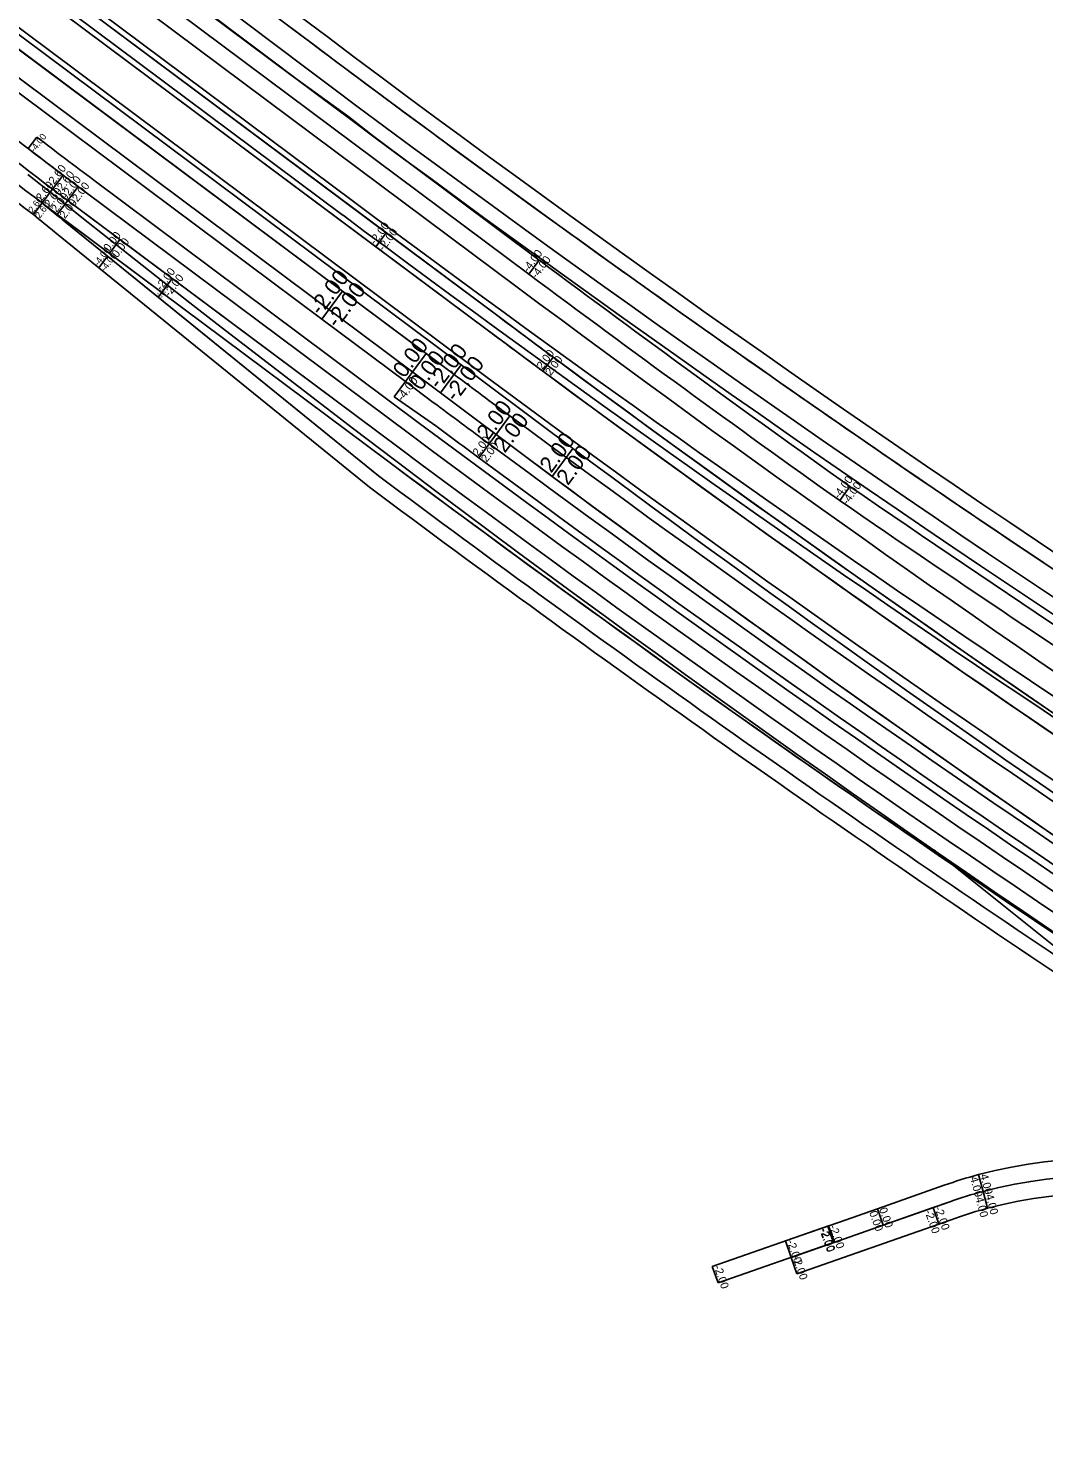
# Model space of a CAD drawing. Extents: x 2342222 to 2351711, y 366548 to 372860.
# Drawn here: x 2344990 to 2345691, y 369795 to 370762 of the extents above; entities that cross this region are included whole.
import ezdxf

# ---------------------------------------------------------------- set-up
doc = ezdxf.new("R2010")
doc.units = 0
for name, color, linetype in [('RD_HC_Cl', 7, 'Continuous'), ('RD_PD_Final_LnLine', 7, 'Continuous'), ('RD_PD_PaveShd', 7, 'Continuous'), ('RD_PD_SuperShp_BL_EB_526', 7, 'Continuous'), ('RD_PD_SuperShp_BL_WB_526', 7, 'Continuous'), ('RD_PD_SuperShp_EB_526', 7, 'Continuous'), ('RD_PD_SuperShp_LINE-A', 7, 'Continuous'), ('RD_PD_SuperShp_REL_L-2118', 7, 'Continuous'), ('RD_PD_SuperShp_REL_LINE-3', 7, 'Continuous'), ('RD_PD_SuperShp_WB_526', 7, 'Continuous')]:
    doc.layers.add(name, color=color, linetype=linetype)

msp = doc.modelspace()

# ---------------------------------------------------------------- linework, layer by layer
at = {"layer": 'RD_HC_Cl'}
msp.add_line((2345614.6, 370194.71), (2346103.37, 369803.49), dxfattribs=at)
msp.add_line((2345614.6, 370194.71), (2346103.37, 369803.49), dxfattribs=at)
at = {"layer": 'RD_PD_Final_LnLine'}
msp.add_arc((2351872.76, 379241.01), 11000, 231.263715, 239.178507, dxfattribs=at)
msp.add_arc((2351872.76, 379241.01), 11000, 231.263715, 239.178507, dxfattribs=at)
at = {"layer": 'RD_PD_PaveShd'}
for p, q in [((2344136.54, 371426.71), (2345306.62, 370553.4)), ((2344797.16, 371008.51), (2345171.34, 370729.24)), ((2345171.34, 370729.24), (2345211.17, 370700.4)), ((2345211.17, 370700.4), (2345227.35, 370687.44)), ((2345227.35, 370687.44), (2345342.51, 370601.49)), ((2345556.78, 370445.41), (2345549.83, 370435.63))]:
    msp.add_line(p, q, dxfattribs=at)
for centre, radius, start, end in [((2352152.85, 379726.19), 11445.99, 233.263715, 239.178507), ((2352001.98, 379817.23), 11374.16, 235.482859, 239.334612)]:
    msp.add_arc(centre, radius, start, end, dxfattribs=at)
at = {"layer": 'RD_PD_SuperShp_BL_EB_526'}
for p, q in [((2345290.87, 370532.3), (2344440.98, 371166.63)), ((2344433.75, 371157.05), (2345206.76, 370580.1)), ((2344433.75, 371157.05), (2345283.69, 370522.68)), ((2345192.4, 370560.87), (2344419.29, 371137.89)), ((2345206.76, 370580.1), (2345192.4, 370560.87)), ((2345192.4, 370560.87), (2345206.76, 370580.1)), ((2345206.76, 370580.1), (2345264.46, 370537.04)), ((2345250.1, 370517.8), (2345192.4, 370560.87)), ((2345264.46, 370537.04), (2345250.1, 370517.8)), ((2345250.1, 370517.8), (2345264.46, 370537.04)), ((2345264.46, 370537.04), (2345283.69, 370522.68)), ((2345250.1, 370517.8), (2345242.28, 370507.33)), ((2345250.1, 370517.8), (2345242.28, 370507.33)), ((2345269.34, 370503.45), (2345250.1, 370517.8)), ((2345269.34, 370503.45), (2345250.1, 370517.8)), ((2345242.28, 370507.33), (2345271.02, 370487.23)), ((2345322.22, 370494.05), (2345307.95, 370474.76)), ((2345307.95, 370474.76), (2345322.22, 370494.05)), ((2345307.95, 370474.76), (2345300.81, 370465.11)), ((2345300.81, 370465.11), (2345307.95, 370474.76))]:
    msp.add_line(p, q, dxfattribs=at)
for radius, start, end in [(11472.33, 233.263715, 239.178507), (11484.33, 233.263715, 233.503184), (11484.33, 233.263715, 233.503184), (11508.33, 233.263715, 233.503184), (11508.33, 233.263715, 233.503184), (11484.33, 233.503184, 238.939044), (11484.33, 233.503184, 238.939044), (11520.33, 233.318655, 233.503184), (11508.33, 233.503184, 238.939044), (11508.33, 233.503184, 238.939044), (11520.33, 233.503184, 238.939044)]:
    msp.add_arc((2352152.85, 379726.19), radius, start, end, dxfattribs=at)
at = {"layer": 'RD_PD_SuperShp_BL_WB_526'}
for p, q in [((2345328.15, 370582.25), (2344157.85, 371455.72)), ((2344143.65, 371436.38), (2345313.8, 370563.02)), ((2345236.87, 370620.44), (2344143.65, 371436.38)), ((2344136.54, 371426.71), (2345229.69, 370610.82)), ((2345171.34, 370729.24), (2344797.16, 371008.51)), ((2344790.06, 370998.84), (2345335.33, 370591.87)), ((2345211.17, 370700.4), (2345171.34, 370729.24)), ((2345227.35, 370687.44), (2345211.17, 370700.4)), ((2345342.51, 370601.49), (2345227.35, 370687.44)), ((2345229.69, 370610.82), (2345236.87, 370620.44)), ((2345236.87, 370620.44), (2345229.69, 370610.82)), ((2345313.8, 370563.02), (2345236.87, 370620.44)), ((2345229.69, 370610.82), (2345306.62, 370553.4)), ((2345342.51, 370601.49), (2345335.33, 370591.87)), ((2345335.33, 370591.87), (2345342.51, 370601.49)), ((2345345.02, 370524.87), (2345352.16, 370534.51)), ((2345352.16, 370534.51), (2345345.02, 370524.87)), ((2345556.78, 370445.41), (2345549.83, 370435.63)), ((2345549.83, 370435.63), (2345556.78, 370445.41))]:
    msp.add_line(p, q, dxfattribs=at)
for centre, radius, start, end in [((2352152.85, 379726.19), 11385.99, 233.263715, 234.597692), ((2352152.85, 379726.19), 11397.99, 233.263715, 234.597692), ((2352152.85, 379726.19), 11409.99, 233.263715, 239.178507), ((2352152.85, 379726.19), 11433.99, 233.263715, 239.178507), ((2352152.85, 379726.19), 11433.99, 233.263715, 233.503189), ((2352152.85, 379726.19), 11445.99, 233.263715, 233.503189), ((2352152.85, 379726.19), 11433.99, 233.503189, 238.939025), ((2352152.85, 379726.19), 11445.99, 233.503189, 238.939025), ((2352001.98, 379817.23), 11374.16, 235.482859, 239.334612), ((2352152.85, 379726.19), 11397.99, 234.597692, 234.598626), ((2352001.98, 379817.23), 11386.16, 235.482859, 238.566804)]:
    msp.add_arc(centre, radius, start, end, dxfattribs=at)
at = {"layer": 'RD_PD_SuperShp_EB_526'}
for p, q in [((2345288.58, 370529.22), (2343854.12, 371599.86)), ((2344510.11, 371080.3), (2345274.23, 370509.99)), ((2345274.23, 370509.99), (2345288.58, 370529.22)), ((2345288.58, 370529.22), (2345274.23, 370509.99)), ((2345352.79, 370481.3), (2345288.58, 370529.22)), ((2345274.23, 370509.99), (2345338.44, 370462.06)), ((2345351.44, 370452.37), (2345365.64, 370471.72)), ((2345365.64, 370471.72), (2345351.44, 370452.37))]:
    msp.add_line(p, q, dxfattribs=at)
for radius, start, end in [(11459.16, 233.263715, 233.343819), (11459.16, 233.343819, 238.698285), (11483.16, 233.263715, 233.344655), (11483.16, 233.263715, 239.178507), (11483.16, 233.344655, 238.6991)]:
    msp.add_arc((2352206.89, 379664.63), radius, start, end, dxfattribs=at)
at = {"layer": 'RD_PD_SuperShp_LINE-A'}
for p, q in [((2344813.13, 371031.79), (2345171.51, 370761.65)), ((2345161.87, 370748.88), (2344803.5, 371019.02)), ((2344803.5, 371019.02), (2345161.87, 370748.88)), ((2344797.48, 371011.03), (2345155.86, 370740.89))]:
    msp.add_line(p, q, dxfattribs=at)
for radius, start, end in [(11390.7, 232.99132, 240.436294), (11400.7, 232.99132, 239.107238), (11400.7, 232.99132, 233.00091), (11400.7, 233.00091, 233.503473), (11416.7, 232.99132, 240.436588), (11416.7, 232.99132, 240.436588), (11426.7, 232.99132, 240.436588), (11400.7, 233.503473, 234.006037), (11400.7, 234.006037, 234.5086), (11400.7, 234.5086, 235.011164), (11400.7, 235.011164, 235.513727), (11400.7, 235.513727, 236.016291), (11400.7, 236.016291, 236.518854)]:
    msp.add_arc((2352034, 379865.62), radius, start, end, dxfattribs=at)
at = {"layer": 'RD_PD_SuperShp_REL_L-2118'}
for p, q in [((2345575.86, 369947.17), (2345621.83, 369963.34)), ((2345645.63, 369970.7), (2345648.73, 369959.11)), ((2345648.73, 369959.11), (2345645.63, 369970.7)), ((2345625.82, 369952.02), (2345579.84, 369935.85)), ((2345614.15, 369947.92), (2345625.82, 369952.02)), ((2345648.73, 369959.11), (2345651.84, 369947.52)), ((2345651.84, 369947.52), (2345648.73, 369959.11)), ((2345549.01, 369937.72), (2345575.86, 369947.17)), ((2345552.97, 369926.39), (2345614.15, 369947.92)), ((2345575.86, 369947.17), (2345579.84, 369935.85)), ((2345579.84, 369935.85), (2345575.86, 369947.17)), ((2345614.15, 369947.92), (2345618.13, 369936.6)), ((2345618.13, 369936.6), (2345614.15, 369947.92)), ((2345461.85, 369907.43), (2345542.12, 369935.39)), ((2345512.26, 369924.93), (2345541.59, 369935.14)), ((2345541.59, 369935.14), (2345549.01, 369937.72)), ((2345541.59, 369935.14), (2345545.53, 369923.8)), ((2345545.53, 369923.8), (2345541.59, 369935.14)), ((2345542.12, 369935.39), (2345546.07, 369924.06)), ((2345579.84, 369935.85), (2345552.97, 369926.39)), ((2345618.13, 369936.6), (2345556.94, 369915.07)), ((2345629.8, 369940.7), (2345618.13, 369936.6)), ((2345546.07, 369924.06), (2345465.8, 369896.1)), ((2345516.21, 369913.59), (2345512.26, 369924.93)), ((2345516.21, 369913.59), (2345552.97, 369926.39)), ((2345545.53, 369923.8), (2345516.21, 369913.59)), ((2345552.97, 369926.39), (2345545.53, 369923.8)), ((2345520.16, 369902.26), (2345516.21, 369913.59)), ((2345556.94, 369915.07), (2345520.16, 369902.26)), ((2345465.8, 369896.1), (2345461.85, 369907.43))]:
    msp.add_line(p, q, dxfattribs=at)
for radius, start, end in [(325, 40.72447, 104.99093), (325, 104.99093, 109.3829), (313, 40.72447, 104.99093), (313, 40.72447, 104.99093), (313, 104.99093, 109.3829), (313, 104.99093, 109.3829), (301, 40.72447, 104.99093), (301, 104.99093, 109.3829)]:
    msp.add_arc((2345729.69, 369656.76), radius, start, end, dxfattribs=at)
at = {"layer": 'RD_PD_SuperShp_REL_LINE-3'}
for p, q in [((2344995.89, 370686.39), (2344989.81, 370678.45)), ((2345006.7, 370650.55), (2345013.92, 370660.13)), ((2345006.7, 370650.55), (2345013.92, 370660.13)), ((2345006.7, 370650.55), (2344999.48, 370640.97)), ((2344999.48, 370640.97), (2345006.7, 370650.55)), ((2345024.29, 370652.35), (2345017.09, 370642.74)), ((2345017.09, 370642.74), (2345024.29, 370652.35)), ((2345029.21, 370648.67), (2345253.04, 370481.61)), ((2345029.21, 370648.67), (2345253.04, 370481.61)), ((2345259.02, 370489.62), (2345035.19, 370656.68)), ((2344999.48, 370640.97), (2344993.42, 370632.93)), ((2344999.48, 370640.97), (2344993.46, 370632.98)), ((2345017.09, 370642.74), (2345009.9, 370633.14)), ((2345017.09, 370642.74), (2345009.9, 370633.14)), ((2345245.86, 370471.99), (2345022.04, 370639.05)), ((2345053.15, 370615.82), (2345022.04, 370639.05)), ((2345009.9, 370633.14), (2345009.56, 370632.68)), ((2345014.54, 370628.63), (2345079.54, 370575.94)), ((2345044.55, 370604.3), (2345014.54, 370628.63)), ((2345014.86, 370629.43), (2345045.98, 370606.21)), ((2345082.04, 370579.29), (2345014.86, 370629.43)), ((2345008.24, 370620.86), (2345038.57, 370596.28)), ((2345045.98, 370606.21), (2345053.15, 370615.82)), ((2345053.15, 370615.82), (2345045.98, 370606.21)), ((2345089.22, 370588.91), (2345053.15, 370615.82)), ((2345038.57, 370596.28), (2345044.55, 370604.3)), ((2345044.55, 370604.3), (2345038.57, 370596.28)), ((2345231.51, 370452.76), (2345044.55, 370604.3)), ((2345045.98, 370606.21), (2345082.04, 370579.29)), ((2345038.57, 370596.28), (2345225.36, 370444.86)), ((2345082.04, 370579.29), (2345089.22, 370588.91)), ((2345082.04, 370579.29), (2345089.22, 370588.91)), ((2345089.22, 370588.91), (2345245.86, 370471.99)), ((2345079.54, 370575.94), (2345082.04, 370579.29)), ((2345082.04, 370579.29), (2345079.54, 370575.94)), ((2345079.54, 370575.94), (2345231.51, 370452.76)), ((2345238.68, 370462.38), (2345082.04, 370579.29)), ((2345238.68, 370462.38), (2345082.04, 370579.29))]:
    msp.add_line(p, q, dxfattribs=at)
for centre, radius, start, end in [((2347422.04, 373854.65), 4000.5, 229.80569, 232.98998), ((2347422.04, 373854.65), 4012.5, 229.80569, 232.98998), ((2347422.04, 373854.65), 4012.5, 229.80569, 232.98998), ((2347422.04, 373854.65), 4024.5, 229.80569, 232.98998), ((2347422.04, 373854.65), 4024.5, 229.80569, 232.98998), ((2347422.04, 373854.65), 4034.5, 229.80569, 232.98998), ((2347422.04, 373854.65), 3990.5, 232.55632, 233.26372), ((2347422.04, 373854.65), 4000.5, 232.55632, 233.26372), ((2347422.04, 373854.65), 4000.5, 232.98998, 233.17561), ((2347422.04, 373854.65), 4012.5, 232.98998, 233.17561), ((2347422.04, 373854.65), 4012.5, 232.98998, 233.17561), ((2347422.04, 373854.65), 4000.5, 233.17561, 233.26372), ((2347578.46, 373791.82), 4071.79, 230.69958, 230.88325), ((2347422.04, 373854.65), 4024.5, 232.98998, 233.17561), ((2347422.04, 373854.65), 4012.5, 233.17561, 233.26372), ((2347422.04, 373854.65), 4012.5, 233.17561, 233.26372), ((2347578.46, 373791.82), 4081.79, 230.70522, 230.97355), ((2347578.46, 373791.82), 4071.79, 230.88325, 230.97356), ((2347578.46, 373791.82), 4071.79, 230.88325, 230.97356), ((2347422.04, 373854.65), 4024.5, 233.17561, 233.26372), ((2347422.04, 373854.65), 4024.5, 233.17561, 233.26372), ((2352152.85, 379726.19), 11525.58, 233.263715, 239.178507), ((2352152.85, 379726.19), 11535.58, 233.263715, 239.178507), ((2352152.85, 379726.19), 11535.58, 233.263715, 239.178507), ((2352152.85, 379726.19), 11547.58, 233.263715, 239.178507), ((2352152.85, 379726.19), 11547.58, 233.263715, 239.178507), ((2352152.85, 379726.19), 11559.58, 233.263715, 239.178507), ((2352152.85, 379726.19), 11559.58, 233.263715, 236.167284), ((2352152.85, 379726.19), 11581.58, 233.262725, 236.165989), ((2352152.85, 379726.19), 11571.58, 233.263715, 236.167274), ((2352152.85, 379726.19), 11571.58, 233.263715, 236.167274)]:
    msp.add_arc(centre, radius, start, end, dxfattribs=at)
at = {"layer": 'RD_PD_SuperShp_WB_526'}
for p, q in [((2345214.29, 370642.07), (2342246.73, 372856.95)), ((2342239.55, 372847.33), (2345207.11, 370632.45))]:
    msp.add_line(p, q, dxfattribs=at)
for radius in [11447.16, 11459.16]:
    msp.add_arc((2352061.21, 379815.79), radius, 233.263715, 239.178507, dxfattribs=at)

# ---------------------------------------------------------------- texts
at = {"layer": 'RD_PD_SuperShp_BL_EB_526'}
for s, height, rotation, p in [('-2.00', 11.04, 53.26372, (2345191.63, 370562.64)), ('-2.00', 11.04, 53.26372, (2345203.17, 370554.03)), ('0.00', 11.04, 53.26372, (2345249.33, 370519.58)), ('0.00', 11.04, 53.26372, (2345260.87, 370510.96)), ('-4.00', 6.014, 53.26372, (2345248.22, 370503.7)), ('2.00', 11.04, 53.50318, (2345307.17, 370476.53)), ('2.00', 11.04, 53.50318, (2345318.74, 370467.96)), ('2.00', 5.52, 53.50318, (2345300.42, 370466)), ('2.00', 5.52, 53.50318, (2345306.21, 370461.71))]:
    msp.add_text(s, height=height, rotation=rotation, dxfattribs=at).set_placement(p)
at = {"layer": 'RD_PD_SuperShp_BL_WB_526'}
for s, height, rotation, p in [('-2.00', 5.52, 53.26372, (2345229.3, 370611.71)), ('-2.00', 5.52, 53.26372, (2345235.07, 370607.4)), ('-4.00', 5.52, 53.26201, (2345334.95, 370592.76)), ('-4.00', 5.52, 53.26372, (2345340.72, 370588.45)), ('2.00', 5.52, 53.50319, (2345344.63, 370525.75)), ('2.00', 5.52, 53.50319, (2345350.42, 370521.47)), ('-4.00', 5.52, 54.59769, (2345549.42, 370436.51)), ('-4.00', 5.519, 54.59586, (2345555.32, 370432.38))]:
    msp.add_text(s, height=height, rotation=rotation, dxfattribs=at).set_placement(p)
at = {"layer": 'RD_PD_SuperShp_EB_526'}
for s, rotation, p in [('-2.00', 53.26374, (2345273.45, 370511.76)), ('-2.00', 53.26374, (2345284.99, 370503.15)), ('2.00', 53.74374, (2345350.69, 370454.18)), ('2.00', 53.74374, (2345362.24, 370445.58))]:
    msp.add_text(s, height=11.04, rotation=rotation, dxfattribs=at).set_placement(p)
at = {"layer": 'RD_PD_SuperShp_REL_L-2118'}
for s, rotation, p in [('4.00', 284.99093, (2345646.56, 369970.45)), ('4.00', 284.99093, (2345639.61, 369968.59)), ('-4.00', 284.99093, (2345642.71, 369957)), ('-4.00', 284.99093, (2345649.67, 369958.86)), ('0.00', 289.3829, (2345570.02, 369944.6)), ('0.00', 289.3829, (2345576.81, 369946.99)), ('-2.00', 289.3829, (2345608.31, 369945.35)), ('-2.00', 289.3829, (2345615.1, 369947.74)), ('-2.00', 289.1976, (2345535.74, 369932.59)), ('-2.00', 289.20136, (2345536.27, 369932.84)), ('-2.00', 289.1976, (2345542.54, 369934.96)), ('-2.00', 289.1976, (2345513.22, 369924.75)), ('-2.00', 289.1976, (2345517.16, 369913.42)), ('-2.00', 289.20136, (2345462.8, 369907.26))]:
    msp.add_text(s, height=5.52, rotation=rotation, dxfattribs=at).set_placement(p)
at = {"layer": 'RD_PD_SuperShp_REL_LINE-3'}
for s, height, rotation, p in [('-4.00', 4.6, 52.55632, (2344994.27, 370675.55)), ('-2.60', 5.52, 52.98998, (2345006.32, 370651.44)), ('-2.60', 5.52, 52.98998, (2345012.07, 370647.11)), ('-2.00', 5.52, 53.17561, (2345016.71, 370643.63)), ('2.60', 5.52, 52.98998, (2344999.09, 370641.86)), ('2.60', 5.52, 52.98998, (2345004.84, 370637.52)), ('2.00', 5.52, 53.17561, (2345009.52, 370634.02)), ('-2.00', 5.52, 53.17561, (2345022.47, 370639.32)), ('2.60', 4.6, 52.98998, (2344993.14, 370633.72)), ('2.60', 4.629, 52.98998, (2344997.85, 370629.95)), ('2.00', 5.52, 53.17561, (2345015.28, 370629.71)), ('2.00', 0.265, 53.17561, (2345009.81, 370632.51)), ('0.00', 5.52, 53.26372, (2345045.59, 370607.09)), ('-4.00', 4.604, 53.26372, (2345038.32, 370597.11)), ('0.00', 5.52, 53.26372, (2345051.36, 370602.79)), ('-4.00', 4.604, 53.26372, (2345042.98, 370593.33)), ('-2.00', 5.52, 53.26372, (2345081.65, 370580.18)), ('-2.00', 5.52, 53.26372, (2345087.42, 370575.87)), ('-2.00', 1.922, 53.26372, (2345079.44, 370576.29)), ('-2.00', 1.922, 53.26372, (2345081.38, 370574.71))]:
    msp.add_text(s, height=height, rotation=rotation, dxfattribs=at).set_placement(p)

doc.saveas('drawing.dxf')
